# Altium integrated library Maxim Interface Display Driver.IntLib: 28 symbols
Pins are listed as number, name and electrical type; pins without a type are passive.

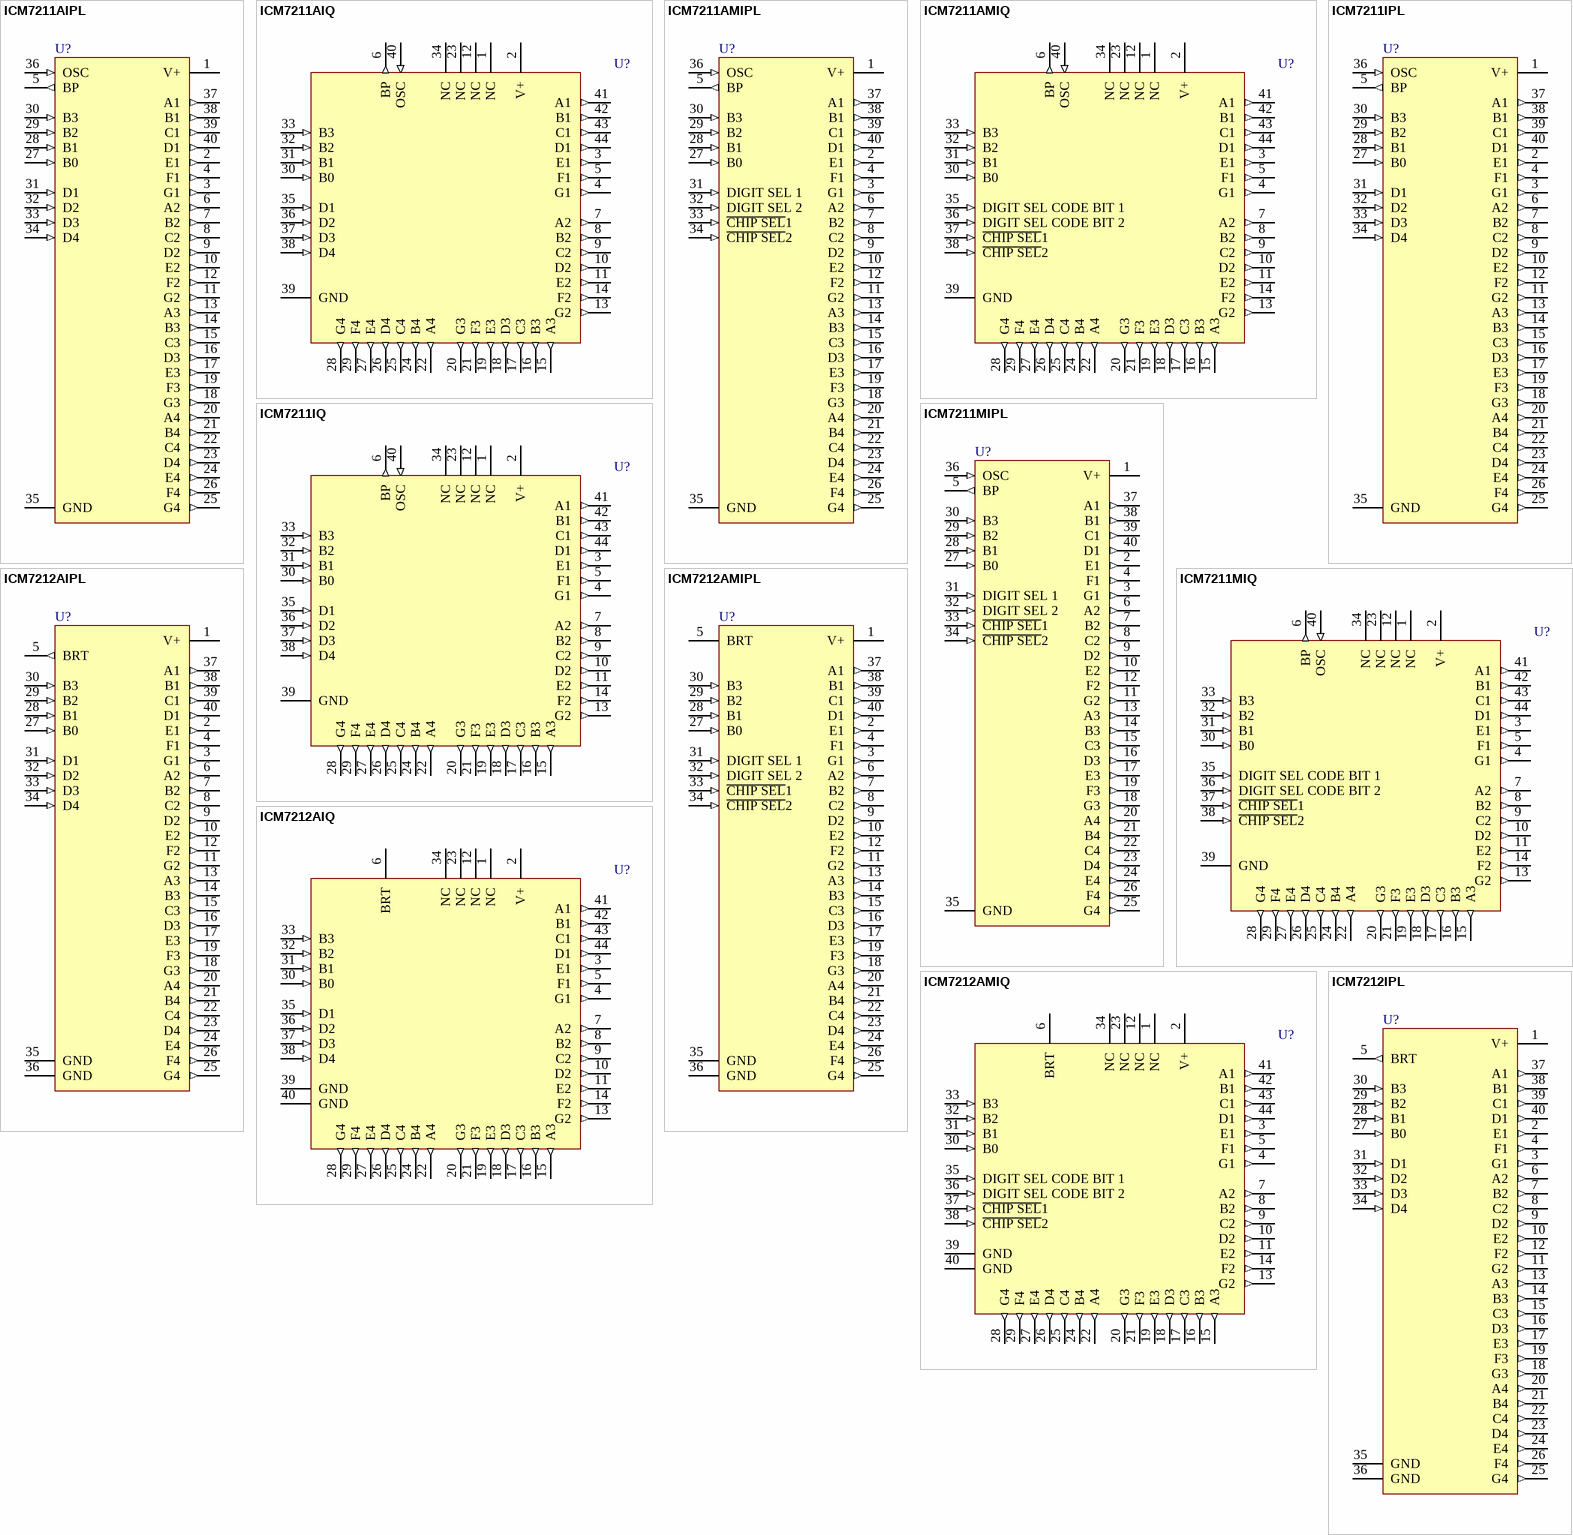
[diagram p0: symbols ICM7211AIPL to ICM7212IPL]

## ICM7211AIPL
designator U?
Four Digit Display Decoder/Driver
footprint PL40 (DIP, 40-Leads, Row Spacing 15.24mm, Pitch 2.54mm, Body 52.08x13.98mm)
3D model PL40 (DIP, 40-Pin, Row Spacing 15.24 mm, Pitch 2.54 mm)
pins: 1 V+ (power), 2 E1 (out), 3 G1 (out), 4 F1 (out), 5 BP (out), 6 A2 (out), 7 B2 (out), 8 C2 (out), 9 D2 (out), 10 E2 (out), 11 G2 (out), 12 F2 (out), 13 A3 (out), 14 B3 (out), 15 C3 (out), 16 D3 (out), 17 E3 (out), 18 G3 (out), 19 F3 (out), 20 A4 (out), 21 B4 (out), 22 C4 (out), 23 D4 (out), 24 E4 (out), 25 G4 (out), 26 F4 (out), 27 B0 (in), 28 B1 (in), 29 B2 (in), 30 B3 (in), 31 D1 (in), 32 D2 (in), 33 D3 (in), 34 D4 (in), 35 GND (power), 36 OSC (in), 37 A1 (out), 38 B1 (out), 39 C1 (out), 40 D1 (out)

## ICM7211AIQ
designator U?
Four Digit Display Decoder/Driver
footprint PLCC44_N (Leaded Chip Carrier, 44-Leads, Body 16.6x16.6mm, Pitch 1.27mm, IPC Medium Density)
footprint PLCC44_L (Leaded Chip Carrier, 44-Leads, Body 16.6x16.6mm, Pitch 1.27mm, IPC High Density)
footprint PLCC44_M (Leaded Chip Carrier, 44-Leads, Body 16.6x16.6mm, Pitch 1.27mm, IPC Low Density)
3D model ICM7211-PLCC44 (44-Pin Leaded Chip Carrier 1.27 mm Pitch)
pins: 1 NC, 2 V+ (power), 3 E1 (out), 4 G1 (out), 5 F1 (out), 6 BP (out), 7 A2 (out), 8 B2 (out), 9 C2 (out), 10 D2 (out), 11 E2 (out), 12 NC, 13 G2 (out), 14 F2 (out), 15 A3 (out), 16 B3 (out), 17 C3 (out), 18 D3 (out), 19 E3 (out), 20 G3 (out), 21 F3 (out), 22 A4 (out), 23 NC, 24 B4 (out), 25 C4 (out), 26 D4 (out), 27 E4 (out), 28 G4 (out), 29 F4 (out), 30 B0 (in), 31 B1 (in), 32 B2 (in), 33 B3 (in), 34 NC, 35 D1 (in), 36 D2 (in), 37 D3 (in), 38 D4 (in), 39 GND (power), 40 OSC (in), 41 A1 (out), 42 B1 (out), 43 C1 (out), 44 D1 (out)

## ICM7211AMIPL
designator U?
Four Digit Display Decoder/Driver
footprint PL40 (DIP, 40-Leads, Row Spacing 15.24mm, Pitch 2.54mm, Body 52.08x13.98mm)
3D model PL40 (DIP, 40-Pin, Row Spacing 15.24 mm, Pitch 2.54 mm)
pins: 1 V+ (power), 2 E1 (out), 3 G1 (out), 4 F1 (out), 5 BP (out), 6 A2 (out), 7 B2 (out), 8 C2 (out), 9 D2 (out), 10 E2 (out), 11 G2 (out), 12 F2 (out), 13 A3 (out), 14 B3 (out), 15 C3 (out), 16 D3 (out), 17 E3 (out), 18 G3 (out), 19 F3 (out), 20 A4 (out), 21 B4 (out), 22 C4 (out), 23 D4 (out), 24 E4 (out), 25 G4 (out), 26 F4 (out), 27 B0 (in), 28 B1 (in), 29 B2 (in), 30 B3 (in), 31 DIGIT SEL 1 (in), 32 DIGIT SEL 2 (in), 33 ~{CHIP SEL}1 (in), 34 ~{CHIP SEL}2 (in), 35 GND (power), 36 OSC (in), 37 A1 (out), 38 B1 (out), 39 C1 (out), 40 D1 (out)

## ICM7211AMIQ
designator U?
Four Digit Display Decoder/Driver
footprint PLCC44_N (Leaded Chip Carrier, 44-Leads, Body 16.6x16.6mm, Pitch 1.27mm, IPC Medium Density)
footprint PLCC44_L (Leaded Chip Carrier, 44-Leads, Body 16.6x16.6mm, Pitch 1.27mm, IPC High Density)
footprint PLCC44_M (Leaded Chip Carrier, 44-Leads, Body 16.6x16.6mm, Pitch 1.27mm, IPC Low Density)
3D model ICM7211-PLCC44 (44-Pin Leaded Chip Carrier 1.27 mm Pitch)
pins: 1 NC, 2 V+ (power), 3 E1 (out), 4 G1 (out), 5 F1 (out), 6 BP (out), 7 A2 (out), 8 B2 (out), 9 C2 (out), 10 D2 (out), 11 E2 (out), 12 NC, 13 G2 (out), 14 F2 (out), 15 A3 (out), 16 B3 (out), 17 C3 (out), 18 D3 (out), 19 E3 (out), 20 G3 (out), 21 F3 (out), 22 A4 (out), 23 NC, 24 B4 (out), 25 C4 (out), 26 D4 (out), 27 E4 (out), 28 G4 (out), 29 F4 (out), 30 B0 (in), 31 B1 (in), 32 B2 (in), 33 B3 (in), 34 NC, 35 DIGIT SEL CODE BIT 1 (in), 36 DIGIT SEL CODE BIT 2 (in), 37 ~{CHIP SEL}1 (in), 38 ~{CHIP SEL}2 (in), 39 GND (power), 40 OSC (in), 41 A1 (out), 42 B1 (out), 43 C1 (out), 44 D1 (out)

## ICM7211IPL
designator U?
Four Digit Display Decoder/Driver
footprint PL40 (DIP, 40-Leads, Row Spacing 15.24mm, Pitch 2.54mm, Body 52.08x13.98mm)
3D model PL40 (DIP, 40-Pin, Row Spacing 15.24 mm, Pitch 2.54 mm)
pins: 1 V+ (power), 2 E1 (out), 3 G1 (out), 4 F1 (out), 5 BP (out), 6 A2 (out), 7 B2 (out), 8 C2 (out), 9 D2 (out), 10 E2 (out), 11 G2 (out), 12 F2 (out), 13 A3 (out), 14 B3 (out), 15 C3 (out), 16 D3 (out), 17 E3 (out), 18 G3 (out), 19 F3 (out), 20 A4 (out), 21 B4 (out), 22 C4 (out), 23 D4 (out), 24 E4 (out), 25 G4 (out), 26 F4 (out), 27 B0 (in), 28 B1 (in), 29 B2 (in), 30 B3 (in), 31 D1 (in), 32 D2 (in), 33 D3 (in), 34 D4 (in), 35 GND (power), 36 OSC (in), 37 A1 (out), 38 B1 (out), 39 C1 (out), 40 D1 (out)

## ICM7211IQ
designator U?
Four Digit Display Decoder/Driver
footprint PLCC44_N (Leaded Chip Carrier, 44-Leads, Body 16.6x16.6mm, Pitch 1.27mm, IPC Medium Density)
footprint PLCC44_L (Leaded Chip Carrier, 44-Leads, Body 16.6x16.6mm, Pitch 1.27mm, IPC High Density)
footprint PLCC44_M (Leaded Chip Carrier, 44-Leads, Body 16.6x16.6mm, Pitch 1.27mm, IPC Low Density)
3D model ICM7211-PLCC44 (44-Pin Leaded Chip Carrier 1.27 mm Pitch)
pins: 1 NC, 2 V+ (power), 3 E1 (out), 4 G1 (out), 5 F1 (out), 6 BP (out), 7 A2 (out), 8 B2 (out), 9 C2 (out), 10 D2 (out), 11 E2 (out), 12 NC, 13 G2 (out), 14 F2 (out), 15 A3 (out), 16 B3 (out), 17 C3 (out), 18 D3 (out), 19 E3 (out), 20 G3 (out), 21 F3 (out), 22 A4 (out), 23 NC, 24 B4 (out), 25 C4 (out), 26 D4 (out), 27 E4 (out), 28 G4 (out), 29 F4 (out), 30 B0 (in), 31 B1 (in), 32 B2 (in), 33 B3 (in), 34 NC, 35 D1 (in), 36 D2 (in), 37 D3 (in), 38 D4 (in), 39 GND (power), 40 OSC (in), 41 A1 (out), 42 B1 (out), 43 C1 (out), 44 D1 (out)

## ICM7211MIPL
designator U?
Four Digit Display Decoder/Driver
footprint PL40 (DIP, 40-Leads, Row Spacing 15.24mm, Pitch 2.54mm, Body 52.08x13.98mm)
3D model PL40 (DIP, 40-Pin, Row Spacing 15.24 mm, Pitch 2.54 mm)
pins: 1 V+ (power), 2 E1 (out), 3 G1 (out), 4 F1 (out), 5 BP (out), 6 A2 (out), 7 B2 (out), 8 C2 (out), 9 D2 (out), 10 E2 (out), 11 G2 (out), 12 F2 (out), 13 A3 (out), 14 B3 (out), 15 C3 (out), 16 D3 (out), 17 E3 (out), 18 G3 (out), 19 F3 (out), 20 A4 (out), 21 B4 (out), 22 C4 (out), 23 D4 (out), 24 E4 (out), 25 G4 (out), 26 F4 (out), 27 B0 (in), 28 B1 (in), 29 B2 (in), 30 B3 (in), 31 DIGIT SEL 1 (in), 32 DIGIT SEL 2 (in), 33 ~{CHIP SEL}1 (in), 34 ~{CHIP SEL}2 (in), 35 GND (power), 36 OSC (in), 37 A1 (out), 38 B1 (out), 39 C1 (out), 40 D1 (out)

## ICM7211MIQ
designator U?
Four Digit Display Decoder/Driver
footprint PLCC44_N (Leaded Chip Carrier, 44-Leads, Body 16.6x16.6mm, Pitch 1.27mm, IPC Medium Density)
footprint PLCC44_L (Leaded Chip Carrier, 44-Leads, Body 16.6x16.6mm, Pitch 1.27mm, IPC High Density)
footprint PLCC44_M (Leaded Chip Carrier, 44-Leads, Body 16.6x16.6mm, Pitch 1.27mm, IPC Low Density)
3D model ICM7211-PLCC44 (44-Pin Leaded Chip Carrier 1.27 mm Pitch)
pins: 1 NC, 2 V+ (power), 3 E1 (out), 4 G1 (out), 5 F1 (out), 6 BP (out), 7 A2 (out), 8 B2 (out), 9 C2 (out), 10 D2 (out), 11 E2 (out), 12 NC, 13 G2 (out), 14 F2 (out), 15 A3 (out), 16 B3 (out), 17 C3 (out), 18 D3 (out), 19 E3 (out), 20 G3 (out), 21 F3 (out), 22 A4 (out), 23 NC, 24 B4 (out), 25 C4 (out), 26 D4 (out), 27 E4 (out), 28 G4 (out), 29 F4 (out), 30 B0 (in), 31 B1 (in), 32 B2 (in), 33 B3 (in), 34 NC, 35 DIGIT SEL CODE BIT 1 (in), 36 DIGIT SEL CODE BIT 2 (in), 37 ~{CHIP SEL}1 (in), 38 ~{CHIP SEL}2 (in), 39 GND (power), 40 OSC (in), 41 A1 (out), 42 B1 (out), 43 C1 (out), 44 D1 (out)

## ICM7212AIPL
designator U?
Four Digit Display Decoder/Driver
footprint PL40 (DIP, 40-Leads, Row Spacing 15.24mm, Pitch 2.54mm, Body 52.08x13.98mm)
3D model PL40 (DIP, 40-Pin, Row Spacing 15.24 mm, Pitch 2.54 mm)
pins: 1 V+ (power), 2 E1 (out), 3 G1 (out), 4 F1 (out), 5 BRT (out), 6 A2 (out), 7 B2 (out), 8 C2 (out), 9 D2 (out), 10 E2 (out), 11 G2 (out), 12 F2 (out), 13 A3 (out), 14 B3 (out), 15 C3 (out), 16 D3 (out), 17 E3 (out), 18 G3 (out), 19 F3 (out), 20 A4 (out), 21 B4 (out), 22 C4 (out), 23 D4 (out), 24 E4 (out), 25 G4 (out), 26 F4 (out), 27 B0 (in), 28 B1 (in), 29 B2 (in), 30 B3 (in), 31 D1 (in), 32 D2 (in), 33 D3 (in), 34 D4 (in), 35 GND (power), 36 GND (power), 37 A1 (out), 38 B1 (out), 39 C1 (out), 40 D1 (out)

## ICM7212AIQ
designator U?
Four Digit Display Decoder/Driver
footprint PLCC44_N (Leaded Chip Carrier, 44-Leads, Body 16.6x16.6mm, Pitch 1.27mm, IPC Medium Density)
footprint PLCC44_L (Leaded Chip Carrier, 44-Leads, Body 16.6x16.6mm, Pitch 1.27mm, IPC High Density)
footprint PLCC44_M (Leaded Chip Carrier, 44-Leads, Body 16.6x16.6mm, Pitch 1.27mm, IPC Low Density)
3D model ICM7212-PLCC44 (44-Pin Leaded Chip Carrier 1.27 mm Pitch)
pins: 1 NC, 2 V+ (power), 3 E1 (out), 4 G1 (out), 5 F1 (out), 6 BRT, 7 A2 (out), 8 B2 (out), 9 C2 (out), 10 D2 (out), 11 E2 (out), 12 NC, 13 G2 (out), 14 F2 (out), 15 A3 (out), 16 B3 (out), 17 C3 (out), 18 D3 (out), 19 E3 (out), 20 G3 (out), 21 F3 (out), 22 A4 (out), 23 NC, 24 B4 (out), 25 C4 (out), 26 D4 (out), 27 E4 (out), 28 G4 (out), 29 F4 (out), 30 B0 (in), 31 B1 (in), 32 B2 (in), 33 B3 (in), 34 NC, 35 D1 (in), 36 D2 (in), 37 D3 (in), 38 D4 (in), 39 GND (power), 40 GND (power), 41 A1 (out), 42 B1 (out), 43 C1 (out), 44 D1 (out)

## ICM7212AMIPL
designator U?
Four Digit Display Decoder/Driver
footprint PL40 (DIP, 40-Leads, Row Spacing 15.24mm, Pitch 2.54mm, Body 52.08x13.98mm)
3D model PL40 (DIP, 40-Pin, Row Spacing 15.24 mm, Pitch 2.54 mm)
pins: 1 V+ (power), 2 E1 (out), 3 G1 (out), 4 F1 (out), 5 BRT, 6 A2 (out), 7 B2 (out), 8 C2 (out), 9 D2 (out), 10 E2 (out), 11 G2 (out), 12 F2 (out), 13 A3 (out), 14 B3 (out), 15 C3 (out), 16 D3 (out), 17 E3 (out), 18 G3 (out), 19 F3 (out), 20 A4 (out), 21 B4 (out), 22 C4 (out), 23 D4 (out), 24 E4 (out), 25 G4 (out), 26 F4 (out), 27 B0 (in), 28 B1 (in), 29 B2 (in), 30 B3 (in), 31 DIGIT SEL 1 (in), 32 DIGIT SEL 2 (in), 33 ~{CHIP SEL}1 (in), 34 ~{CHIP SEL}2 (in), 35 GND (power), 36 GND (power), 37 A1 (out), 38 B1 (out), 39 C1 (out), 40 D1 (out)

## ICM7212AMIQ
designator U?
Four Digit Display Decoder/Driver
footprint PLCC44_N (Leaded Chip Carrier, 44-Leads, Body 16.6x16.6mm, Pitch 1.27mm, IPC Medium Density)
footprint PLCC44_L (Leaded Chip Carrier, 44-Leads, Body 16.6x16.6mm, Pitch 1.27mm, IPC High Density)
footprint PLCC44_M (Leaded Chip Carrier, 44-Leads, Body 16.6x16.6mm, Pitch 1.27mm, IPC Low Density)
3D model ICM7212-PLCC44 (44-Pin Leaded Chip Carrier 1.27 mm Pitch)
pins: 1 NC, 2 V+ (power), 3 E1 (out), 4 G1 (out), 5 F1 (out), 6 BRT, 7 A2 (out), 8 B2 (out), 9 C2 (out), 10 D2 (out), 11 E2 (out), 12 NC, 13 G2 (out), 14 F2 (out), 15 A3 (out), 16 B3 (out), 17 C3 (out), 18 D3 (out), 19 E3 (out), 20 G3 (out), 21 F3 (out), 22 A4 (out), 23 NC, 24 B4 (out), 25 C4 (out), 26 D4 (out), 27 E4 (out), 28 G4 (out), 29 F4 (out), 30 B0 (in), 31 B1 (in), 32 B2 (in), 33 B3 (in), 34 NC, 35 DIGIT SEL CODE BIT 1 (in), 36 DIGIT SEL CODE BIT 2 (in), 37 ~{CHIP SEL}1 (in), 38 ~{CHIP SEL}2 (in), 39 GND (power), 40 GND (power), 41 A1 (out), 42 B1 (out), 43 C1 (out), 44 D1 (out)

## ICM7212IPL
designator U?
Four Digit Display Decoder/Driver
footprint PL40 (DIP, 40-Leads, Row Spacing 15.24mm, Pitch 2.54mm, Body 52.08x13.98mm)
3D model PL40 (DIP, 40-Pin, Row Spacing 15.24 mm, Pitch 2.54 mm)
pins: 1 V+ (power), 2 E1 (out), 3 G1 (out), 4 F1 (out), 5 BRT (out), 6 A2 (out), 7 B2 (out), 8 C2 (out), 9 D2 (out), 10 E2 (out), 11 G2 (out), 12 F2 (out), 13 A3 (out), 14 B3 (out), 15 C3 (out), 16 D3 (out), 17 E3 (out), 18 G3 (out), 19 F3 (out), 20 A4 (out), 21 B4 (out), 22 C4 (out), 23 D4 (out), 24 E4 (out), 25 G4 (out), 26 F4 (out), 27 B0 (in), 28 B1 (in), 29 B2 (in), 30 B3 (in), 31 D1 (in), 32 D2 (in), 33 D3 (in), 34 D4 (in), 35 GND (power), 36 GND (power), 37 A1 (out), 38 B1 (out), 39 C1 (out), 40 D1 (out)

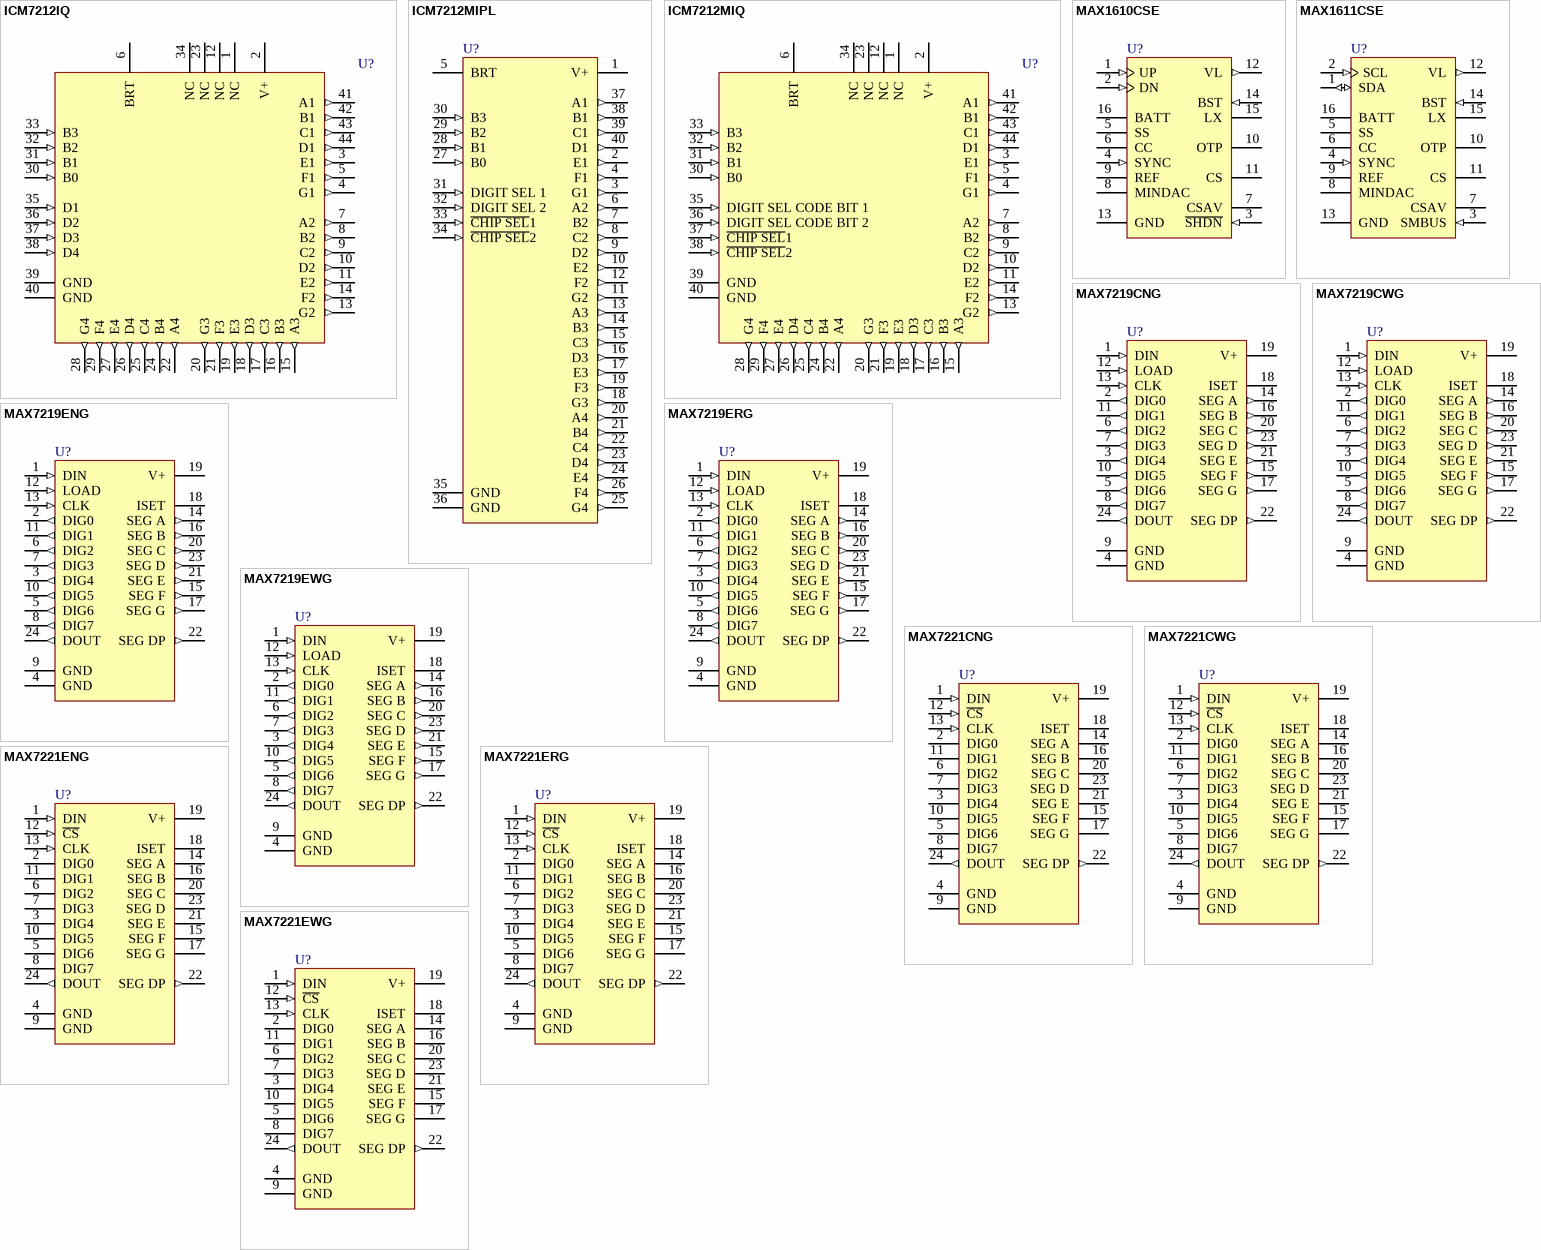
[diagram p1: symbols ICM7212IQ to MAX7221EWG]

## ICM7212IQ
designator U?
Four Digit Display Decoder/Driver
footprint PLCC44_N (Leaded Chip Carrier, 44-Leads, Body 16.6x16.6mm, Pitch 1.27mm, IPC Medium Density)
footprint PLCC44_L (Leaded Chip Carrier, 44-Leads, Body 16.6x16.6mm, Pitch 1.27mm, IPC High Density)
footprint PLCC44_M (Leaded Chip Carrier, 44-Leads, Body 16.6x16.6mm, Pitch 1.27mm, IPC Low Density)
3D model ICM7212-PLCC44 (44-Pin Leaded Chip Carrier 1.27 mm Pitch)
pins: 1 NC, 2 V+ (power), 3 E1 (out), 4 G1 (out), 5 F1 (out), 6 BRT, 7 A2 (out), 8 B2 (out), 9 C2 (out), 10 D2 (out), 11 E2 (out), 12 NC, 13 G2 (out), 14 F2 (out), 15 A3 (out), 16 B3 (out), 17 C3 (out), 18 D3 (out), 19 E3 (out), 20 G3 (out), 21 F3 (out), 22 A4 (out), 23 NC, 24 B4 (out), 25 C4 (out), 26 D4 (out), 27 E4 (out), 28 G4 (out), 29 F4 (out), 30 B0 (in), 31 B1 (in), 32 B2 (in), 33 B3 (in), 34 NC, 35 D1 (in), 36 D2 (in), 37 D3 (in), 38 D4 (in), 39 GND (power), 40 GND (power), 41 A1 (out), 42 B1 (out), 43 C1 (out), 44 D1 (out)

## ICM7212MIPL
designator U?
Four Digit Display Decoder/Driver
footprint PL40 (DIP, 40-Leads, Row Spacing 15.24mm, Pitch 2.54mm, Body 52.08x13.98mm)
3D model PL40 (DIP, 40-Pin, Row Spacing 15.24 mm, Pitch 2.54 mm)
pins: 1 V+ (power), 2 E1 (out), 3 G1 (out), 4 F1 (out), 5 BRT, 6 A2 (out), 7 B2 (out), 8 C2 (out), 9 D2 (out), 10 E2 (out), 11 G2 (out), 12 F2 (out), 13 A3 (out), 14 B3 (out), 15 C3 (out), 16 D3 (out), 17 E3 (out), 18 G3 (out), 19 F3 (out), 20 A4 (out), 21 B4 (out), 22 C4 (out), 23 D4 (out), 24 E4 (out), 25 G4 (out), 26 F4 (out), 27 B0 (in), 28 B1 (in), 29 B2 (in), 30 B3 (in), 31 DIGIT SEL 1 (in), 32 DIGIT SEL 2 (in), 33 ~{CHIP SEL}1 (in), 34 ~{CHIP SEL}2 (in), 35 GND (power), 36 GND (power), 37 A1 (out), 38 B1 (out), 39 C1 (out), 40 D1 (out)

## ICM7212MIQ
designator U?
Four Digit Display Decoder/Driver
footprint PLCC44_N (Leaded Chip Carrier, 44-Leads, Body 16.6x16.6mm, Pitch 1.27mm, IPC Medium Density)
footprint PLCC44_L (Leaded Chip Carrier, 44-Leads, Body 16.6x16.6mm, Pitch 1.27mm, IPC High Density)
footprint PLCC44_M (Leaded Chip Carrier, 44-Leads, Body 16.6x16.6mm, Pitch 1.27mm, IPC Low Density)
3D model ICM7212-PLCC44 (44-Pin Leaded Chip Carrier 1.27 mm Pitch)
pins: 1 NC, 2 V+ (power), 3 E1 (out), 4 G1 (out), 5 F1 (out), 6 BRT, 7 A2 (out), 8 B2 (out), 9 C2 (out), 10 D2 (out), 11 E2 (out), 12 NC, 13 G2 (out), 14 F2 (out), 15 A3 (out), 16 B3 (out), 17 C3 (out), 18 D3 (out), 19 E3 (out), 20 G3 (out), 21 F3 (out), 22 A4 (out), 23 NC, 24 B4 (out), 25 C4 (out), 26 D4 (out), 27 E4 (out), 28 G4 (out), 29 F4 (out), 30 B0 (in), 31 B1 (in), 32 B2 (in), 33 B3 (in), 34 NC, 35 DIGIT SEL CODE BIT 1 (in), 36 DIGIT SEL CODE BIT 2 (in), 37 ~{CHIP SEL}1 (in), 38 ~{CHIP SEL}2 (in), 39 GND (power), 40 GND (power), 41 A1 (out), 42 B1 (out), 43 C1 (out), 44 D1 (out)

## MAX1610CSE
designator U?
Digitally Controlled CCFL Backlight Power Supplies
footprint NSO16_N (SOIC, 16-Leads, Body 9.9x3.9mm, Pitch 1.27mm, IPC Medium Density)
footprint NSO16_L (SOIC, 16-Leads, Body 9.9x3.9mm, Pitch 1.27mm, IPC High Density)
footprint NSO16_M (SOIC, 16-Leads, Body 9.9x3.9mm, Pitch 1.27mm, IPC Low Density)
3D model NSO16 (16-Pin Small Outline Integrated Circuit 1.27 mm Pitch)
pins: 1 UP (in), 2 DN (in), 3 ~{SHDN} (in), 4 SYNC (in), 5 SS, 6 CC, 7 CSAV, 8 MINDAC, 9 REF, 10 OTP, 11 CS, 12 VL (out), 13 GND (power), 14 BST (in), 15 LX, 16 BATT

## MAX1611CSE
designator U?
Digitally Controlled CCFL Backlight Power Supplies
footprint NSO16_N (SOIC, 16-Leads, Body 9.9x3.9mm, Pitch 1.27mm, IPC Medium Density)
footprint NSO16_L (SOIC, 16-Leads, Body 9.9x3.9mm, Pitch 1.27mm, IPC High Density)
footprint NSO16_M (SOIC, 16-Leads, Body 9.9x3.9mm, Pitch 1.27mm, IPC Low Density)
3D model NSO16 (16-Pin Small Outline Integrated Circuit 1.27 mm Pitch)
pins: 1 SDA (io), 2 SCL (in), 3 SMBUS (in), 4 SYNC (in), 5 SS, 6 CC, 7 CSAV, 8 MINDAC, 9 REF, 10 OTP, 11 CS, 12 VL (out), 13 GND (power), 14 BST (in), 15 LX, 16 BATT

## MAX7219CNG
designator U?
Serially Interfaced, 8-Digit LED Display Driver
footprint NG24A (DIP, 24-Leads, Row Spacing 7.62mm, Pitch 2.54mm, Body 30.55x6.99mm)
3D model NG24 (DIP, 24-Pin, Row Spacing 7.62 mm, Pitch 2.54 mm)
pins: 1 DIN (in), 2 DIG0 (out), 3 DIG4 (out), 4 GND (power), 5 DIG6 (out), 6 DIG2 (out), 7 DIG3 (out), 8 DIG7 (out), 9 GND (power), 10 DIG5 (out), 11 DIG1 (out), 12 LOAD (in), 13 CLK (in), 14 SEG A (out), 15 SEG F (out), 16 SEG B (out), 17 SEG G (out), 18 ISET, 19 V+ (power), 20 SEG C (out), 21 SEG E (out), 22 SEG DP (out), 23 SEG D (out), 24 DOUT (out)

## MAX7219CWG
designator U?
Serially Interfaced, 8-Digit LED Display Driver
footprint WSO24_N (SOIC, 24-Leads, Body 15.4x7.5mm, Pitch 1.27mm, IPC Medium Density)
footprint WSO24_L (SOIC, 24-Leads, Body 15.4x7.5mm, Pitch 1.27mm, IPC High Density)
footprint WSO24_M (SOIC, 24-Leads, Body 15.4x7.5mm, Pitch 1.27mm, IPC Low Density)
3D model WSO24 (24-Pin Small Outline Integrated Circuit 1.27 mm Pitch)
pins: 1 DIN (in), 2 DIG0 (out), 3 DIG4 (out), 4 GND (power), 5 DIG6 (out), 6 DIG2 (out), 7 DIG3 (out), 8 DIG7 (out), 9 GND (power), 10 DIG5 (out), 11 DIG1 (out), 12 LOAD (in), 13 CLK (in), 14 SEG A (out), 15 SEG F (out), 16 SEG B (out), 17 SEG G (out), 18 ISET, 19 V+ (power), 20 SEG C (out), 21 SEG E (out), 22 SEG DP (out), 23 SEG D (out), 24 DOUT (out)

## MAX7219ENG
designator U?
Serially Interfaced, 8-Digit LED Display Driver
footprint NG24A (DIP, 24-Leads, Row Spacing 7.62mm, Pitch 2.54mm, Body 30.55x6.99mm)
3D model NG24 (DIP, 24-Pin, Row Spacing 7.62 mm, Pitch 2.54 mm)
pins: 1 DIN (in), 2 DIG0 (out), 3 DIG4 (out), 4 GND (power), 5 DIG6 (out), 6 DIG2 (out), 7 DIG3 (out), 8 DIG7 (out), 9 GND (power), 10 DIG5 (out), 11 DIG1 (out), 12 LOAD (in), 13 CLK (in), 14 SEG A (out), 15 SEG F (out), 16 SEG B (out), 17 SEG G (out), 18 ISET, 19 V+ (power), 20 SEG C (out), 21 SEG E (out), 22 SEG DP (out), 23 SEG D (out), 24 DOUT (out)

## MAX7219ERG
designator U?
Serially Interfaced, 8-Digit LED Display Driver
footprint RG24 (DIP, 24-Leads, Row Spacing 7.62mm, Pitch 2.54mm, Body 31.88x6.73mm)
3D model NG24 (DIP, 24-Pin, Row Spacing 7.62 mm, Pitch 2.54 mm)
pins: 1 DIN (in), 2 DIG0 (out), 3 DIG4 (out), 4 GND (power), 5 DIG6 (out), 6 DIG2 (out), 7 DIG3 (out), 8 DIG7 (out), 9 GND (power), 10 DIG5 (out), 11 DIG1 (out), 12 LOAD (in), 13 CLK (in), 14 SEG A (out), 15 SEG F (out), 16 SEG B (out), 17 SEG G (out), 18 ISET, 19 V+ (power), 20 SEG C (out), 21 SEG E (out), 22 SEG DP (out), 23 SEG D (out), 24 DOUT (out)

## MAX7219EWG
designator U?
Serially Interfaced, 8-Digit LED Display Driver
footprint WSO24_N (SOIC, 24-Leads, Body 15.4x7.5mm, Pitch 1.27mm, IPC Medium Density)
footprint WSO24_L (SOIC, 24-Leads, Body 15.4x7.5mm, Pitch 1.27mm, IPC High Density)
footprint WSO24_M (SOIC, 24-Leads, Body 15.4x7.5mm, Pitch 1.27mm, IPC Low Density)
3D model WSO24 (24-Pin Small Outline Integrated Circuit 1.27 mm Pitch)
pins: 1 DIN (in), 2 DIG0 (out), 3 DIG4 (out), 4 GND (power), 5 DIG6 (out), 6 DIG2 (out), 7 DIG3 (out), 8 DIG7 (out), 9 GND (power), 10 DIG5 (out), 11 DIG1 (out), 12 LOAD (in), 13 CLK (in), 14 SEG A (out), 15 SEG F (out), 16 SEG B (out), 17 SEG G (out), 18 ISET, 19 V+ (power), 20 SEG C (out), 21 SEG E (out), 22 SEG DP (out), 23 SEG D (out), 24 DOUT (out)

## MAX7221CNG
designator U?
Serially Interfaced, 8-Digit LED Display Driver; Note: The 8 digit drivers and the 7 segment drivers are high-impedance when turned off.
footprint NG24A (DIP, 24-Leads, Row Spacing 7.62mm, Pitch 2.54mm, Body 30.55x6.99mm)
3D model NG24 (DIP, 24-Pin, Row Spacing 7.62 mm, Pitch 2.54 mm)
pins: 1 DIN (in), 2 DIG0 (hiz), 3 DIG4 (hiz), 4 GND (power), 5 DIG6 (hiz), 6 DIG2 (hiz), 7 DIG3 (hiz), 8 DIG7 (hiz), 9 GND (power), 10 DIG5 (hiz), 11 DIG1 (hiz), 12 ~{CS} (in), 13 CLK (in), 14 SEG A (hiz), 15 SEG F (hiz), 16 SEG B (hiz), 17 SEG G (hiz), 18 ISET, 19 V+ (power), 20 SEG C (hiz), 21 SEG E (hiz), 22 SEG DP (out), 23 SEG D (hiz), 24 DOUT (out)

## MAX7221CWG
designator U?
Serially Interfaced, 8-Digit LED Display Driver; Note: The 8 digit drivers and the 7 segment drivers are high-impedance when turned off.
footprint WSO24_N (SOIC, 24-Leads, Body 15.4x7.5mm, Pitch 1.27mm, IPC Medium Density)
footprint WSO24_L (SOIC, 24-Leads, Body 15.4x7.5mm, Pitch 1.27mm, IPC High Density)
footprint WSO24_M (SOIC, 24-Leads, Body 15.4x7.5mm, Pitch 1.27mm, IPC Low Density)
3D model WSO24 (24-Pin Small Outline Integrated Circuit 1.27 mm Pitch)
pins: 1 DIN (in), 2 DIG0 (hiz), 3 DIG4 (hiz), 4 GND (power), 5 DIG6 (hiz), 6 DIG2 (hiz), 7 DIG3 (hiz), 8 DIG7 (hiz), 9 GND (power), 10 DIG5 (hiz), 11 DIG1 (hiz), 12 ~{CS} (in), 13 CLK (in), 14 SEG A (hiz), 15 SEG F (hiz), 16 SEG B (hiz), 17 SEG G (hiz), 18 ISET, 19 V+ (power), 20 SEG C (hiz), 21 SEG E (hiz), 22 SEG DP (out), 23 SEG D (hiz), 24 DOUT (out)

## MAX7221ENG
designator U?
Serially Interfaced, 8-Digit LED Display Driver; Note: The 8 digit drivers and the 7 segment drivers are high-impedance when turned off.
footprint NG24A (DIP, 24-Leads, Row Spacing 7.62mm, Pitch 2.54mm, Body 30.55x6.99mm)
3D model NG24 (DIP, 24-Pin, Row Spacing 7.62 mm, Pitch 2.54 mm)
pins: 1 DIN (in), 2 DIG0 (hiz), 3 DIG4 (hiz), 4 GND (power), 5 DIG6 (hiz), 6 DIG2 (hiz), 7 DIG3 (hiz), 8 DIG7 (hiz), 9 GND (power), 10 DIG5 (hiz), 11 DIG1 (hiz), 12 ~{CS} (in), 13 CLK (in), 14 SEG A (hiz), 15 SEG F (hiz), 16 SEG B (hiz), 17 SEG G (hiz), 18 ISET, 19 V+ (power), 20 SEG C (hiz), 21 SEG E (hiz), 22 SEG DP (out), 23 SEG D (hiz), 24 DOUT (out)

## MAX7221ERG
designator U?
Serially Interfaced, 8-Digit LED Display Driver; Note: The 8 digit drivers and the 7 segment drivers are high-impedance when turned off.
footprint RG24 (DIP, 24-Leads, Row Spacing 7.62mm, Pitch 2.54mm, Body 31.88x6.73mm)
3D model NG24 (DIP, 24-Pin, Row Spacing 7.62 mm, Pitch 2.54 mm)
pins: 1 DIN (in), 2 DIG0 (hiz), 3 DIG4 (hiz), 4 GND (power), 5 DIG6 (hiz), 6 DIG2 (hiz), 7 DIG3 (hiz), 8 DIG7 (hiz), 9 GND (power), 10 DIG5 (hiz), 11 DIG1 (hiz), 12 ~{CS} (in), 13 CLK (in), 14 SEG A (hiz), 15 SEG F (hiz), 16 SEG B (hiz), 17 SEG G (hiz), 18 ISET, 19 V+ (power), 20 SEG C (hiz), 21 SEG E (hiz), 22 SEG DP (out), 23 SEG D (hiz), 24 DOUT (out)

## MAX7221EWG
designator U?
Serially Interfaced, 8-Digit LED Display Driver; Note: The 8 digit drivers and the 7 segment drivers are high-impedance when turned off.
footprint WSO24_N (SOIC, 24-Leads, Body 15.4x7.5mm, Pitch 1.27mm, IPC Medium Density)
footprint WSO24_L (SOIC, 24-Leads, Body 15.4x7.5mm, Pitch 1.27mm, IPC High Density)
footprint WSO24_M (SOIC, 24-Leads, Body 15.4x7.5mm, Pitch 1.27mm, IPC Low Density)
3D model WSO24 (24-Pin Small Outline Integrated Circuit 1.27 mm Pitch)
pins: 1 DIN (in), 2 DIG0 (hiz), 3 DIG4 (hiz), 4 GND (power), 5 DIG6 (hiz), 6 DIG2 (hiz), 7 DIG3 (hiz), 8 DIG7 (hiz), 9 GND (power), 10 DIG5 (hiz), 11 DIG1 (hiz), 12 ~{CS} (in), 13 CLK (in), 14 SEG A (hiz), 15 SEG F (hiz), 16 SEG B (hiz), 17 SEG G (hiz), 18 ISET, 19 V+ (power), 20 SEG C (hiz), 21 SEG E (hiz), 22 SEG DP (out), 23 SEG D (hiz), 24 DOUT (out)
